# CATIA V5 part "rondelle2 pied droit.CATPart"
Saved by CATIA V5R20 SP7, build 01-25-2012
Part number: rondelle 2 pied droit
Bounding box of the stored display mesh (mm): x 9.548 to 22.172, y -79 to -65, z -19.353 to -11.487
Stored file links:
  F:\Travaux\Modélisations\CFAO_2011\CFAO_2011_MMS\CFAO_2011_MMS_DONE\CFAO_2011_MMS_jboiteux\Catia\rondelle2 pied droit.CATPart
  U:\finthinkmotion\stepper.CATProduct
  F:\Travaux\Modélisations\CFAO_2011\CFAO_2011_MMS\CFAO_2011_MMS_DONE\CFAO_2011_MMS_jboiteux\Catia\roulement2 pied doit.CATPart
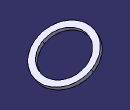
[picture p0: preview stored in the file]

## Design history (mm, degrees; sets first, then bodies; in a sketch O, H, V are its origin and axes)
Set1
  DatumSurface1: linked copy from another document
Body1 (main body)
  Sketch1 on face of DatumSurface1, origin (-2.4622, 0, -4.2647), H (0, 1, 0), V (-0.866, 0, 0.5)
    projected circle E1 centre (-72, -21.4454) radius 7 from edge of DatumSurface1
    projected circle E2 centre (-72, -21.4454) radius 5.5 from edge of DatumSurface1
  Pad1: profile Sketch1, direction (-0.5, 0, -0.866), length 1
